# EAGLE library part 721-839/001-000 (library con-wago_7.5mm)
Serie 721, Stiftleiste (für Leiterplatten) Einlötstift abgewinkelt 1 x 1 mm / Series 721, Male header (for PCBs) Angled solder pin 1 x 1 mm Polzahl / Pole No.: 9 Rastermaß / Pitch: 7.5 mm Bemessungsspannung / Rated Voltage: 630 V Nennstrom / Nominal Current: 12 A Lötstiftlänge: / Solder Pin Length: 3.8 mm Farbe / Color: lichtgrau / light gray Stand: 01.01.2012. Die jeweils aktuellen Daten zu diesem Artikel finden Sie in unserem Produktkatalog, den Sie unter www.wago.com einsehen können. As of: 01/01/2012. Please find the newest data for this article in our product catalogue, which can be viewed under www.wago.com.
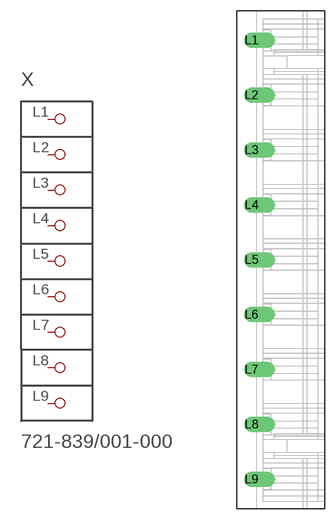
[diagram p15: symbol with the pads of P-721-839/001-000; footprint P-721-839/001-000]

Designator prefix X

## 721-839/001-000  [P-721-839/001-000]
L1  P1
L2  P2
L3  P3
L4  P4
L5  P5
L6  P6
L7  P7
L8  P8
L9  P9

## Footprint P-721-839/001-000 (pad centres in mm)
drill 1.4 offset: L1 -4,30; L2 -4,22.5; L3 -4,15; L4 -4,7.5; L5 -4,0; L6 -4,-7.5; L7 -4,-15; L8 -4,-22.5; L9 -4,-30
